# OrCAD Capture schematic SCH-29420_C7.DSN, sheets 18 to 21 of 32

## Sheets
18 P16_eMMC & SD_CARD: size A2
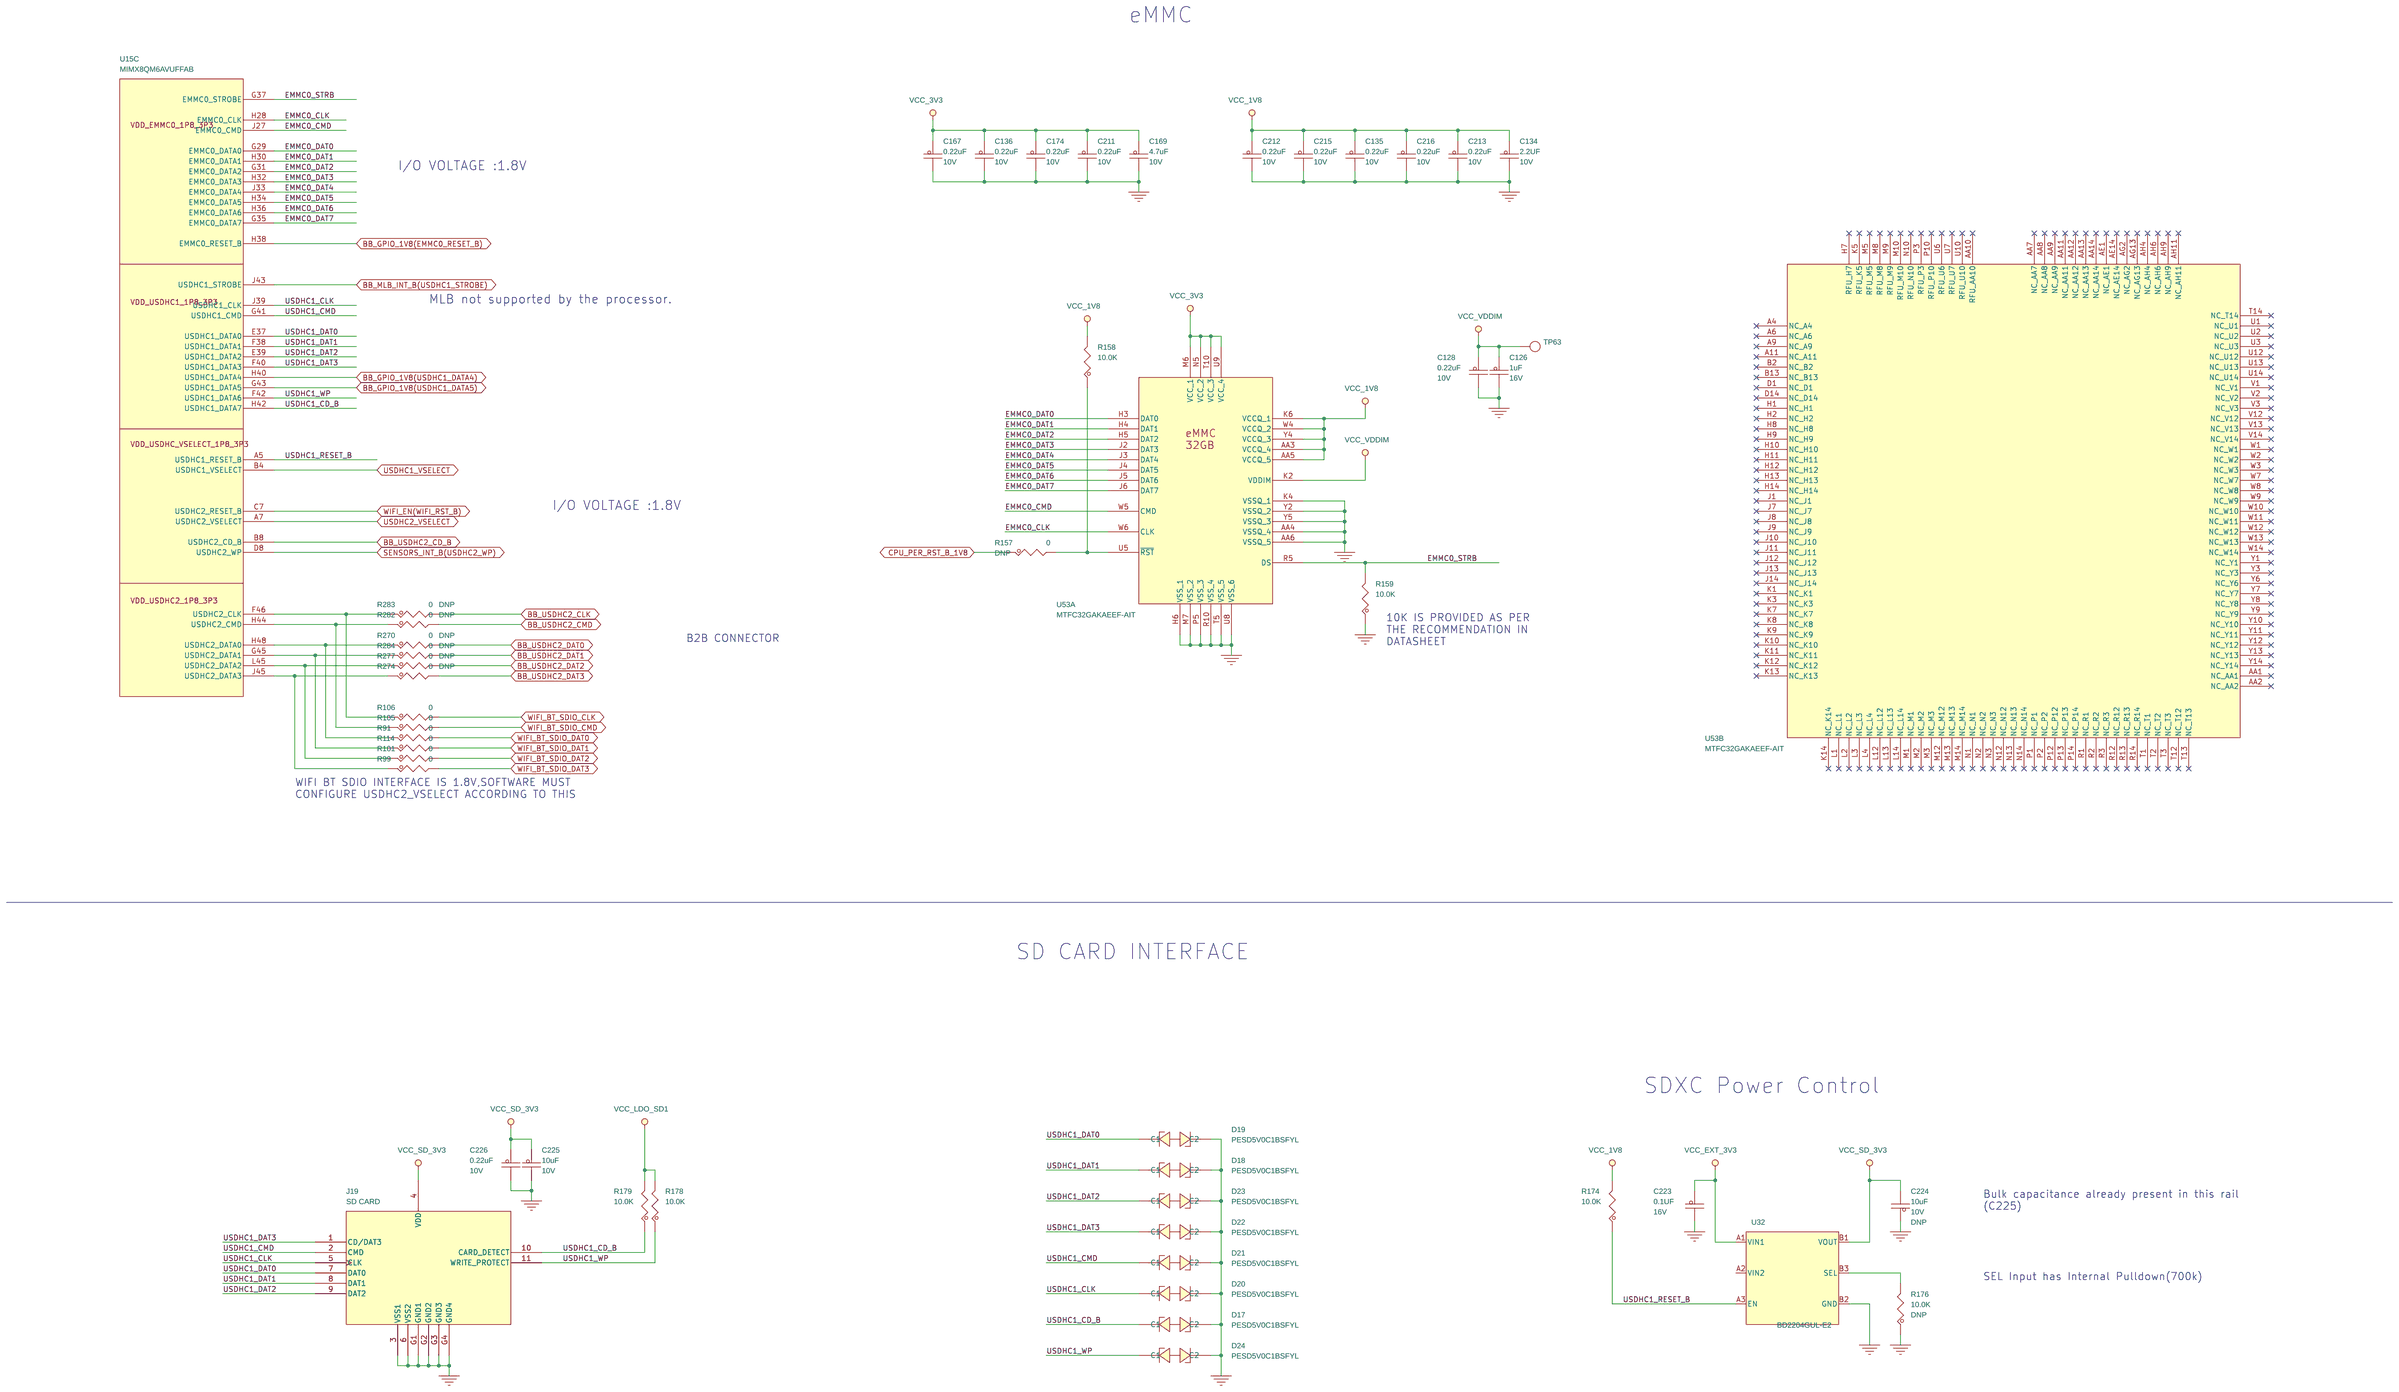
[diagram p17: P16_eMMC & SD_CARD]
19 P17_BOOT_CONFIG & SPI FLASH: size A2
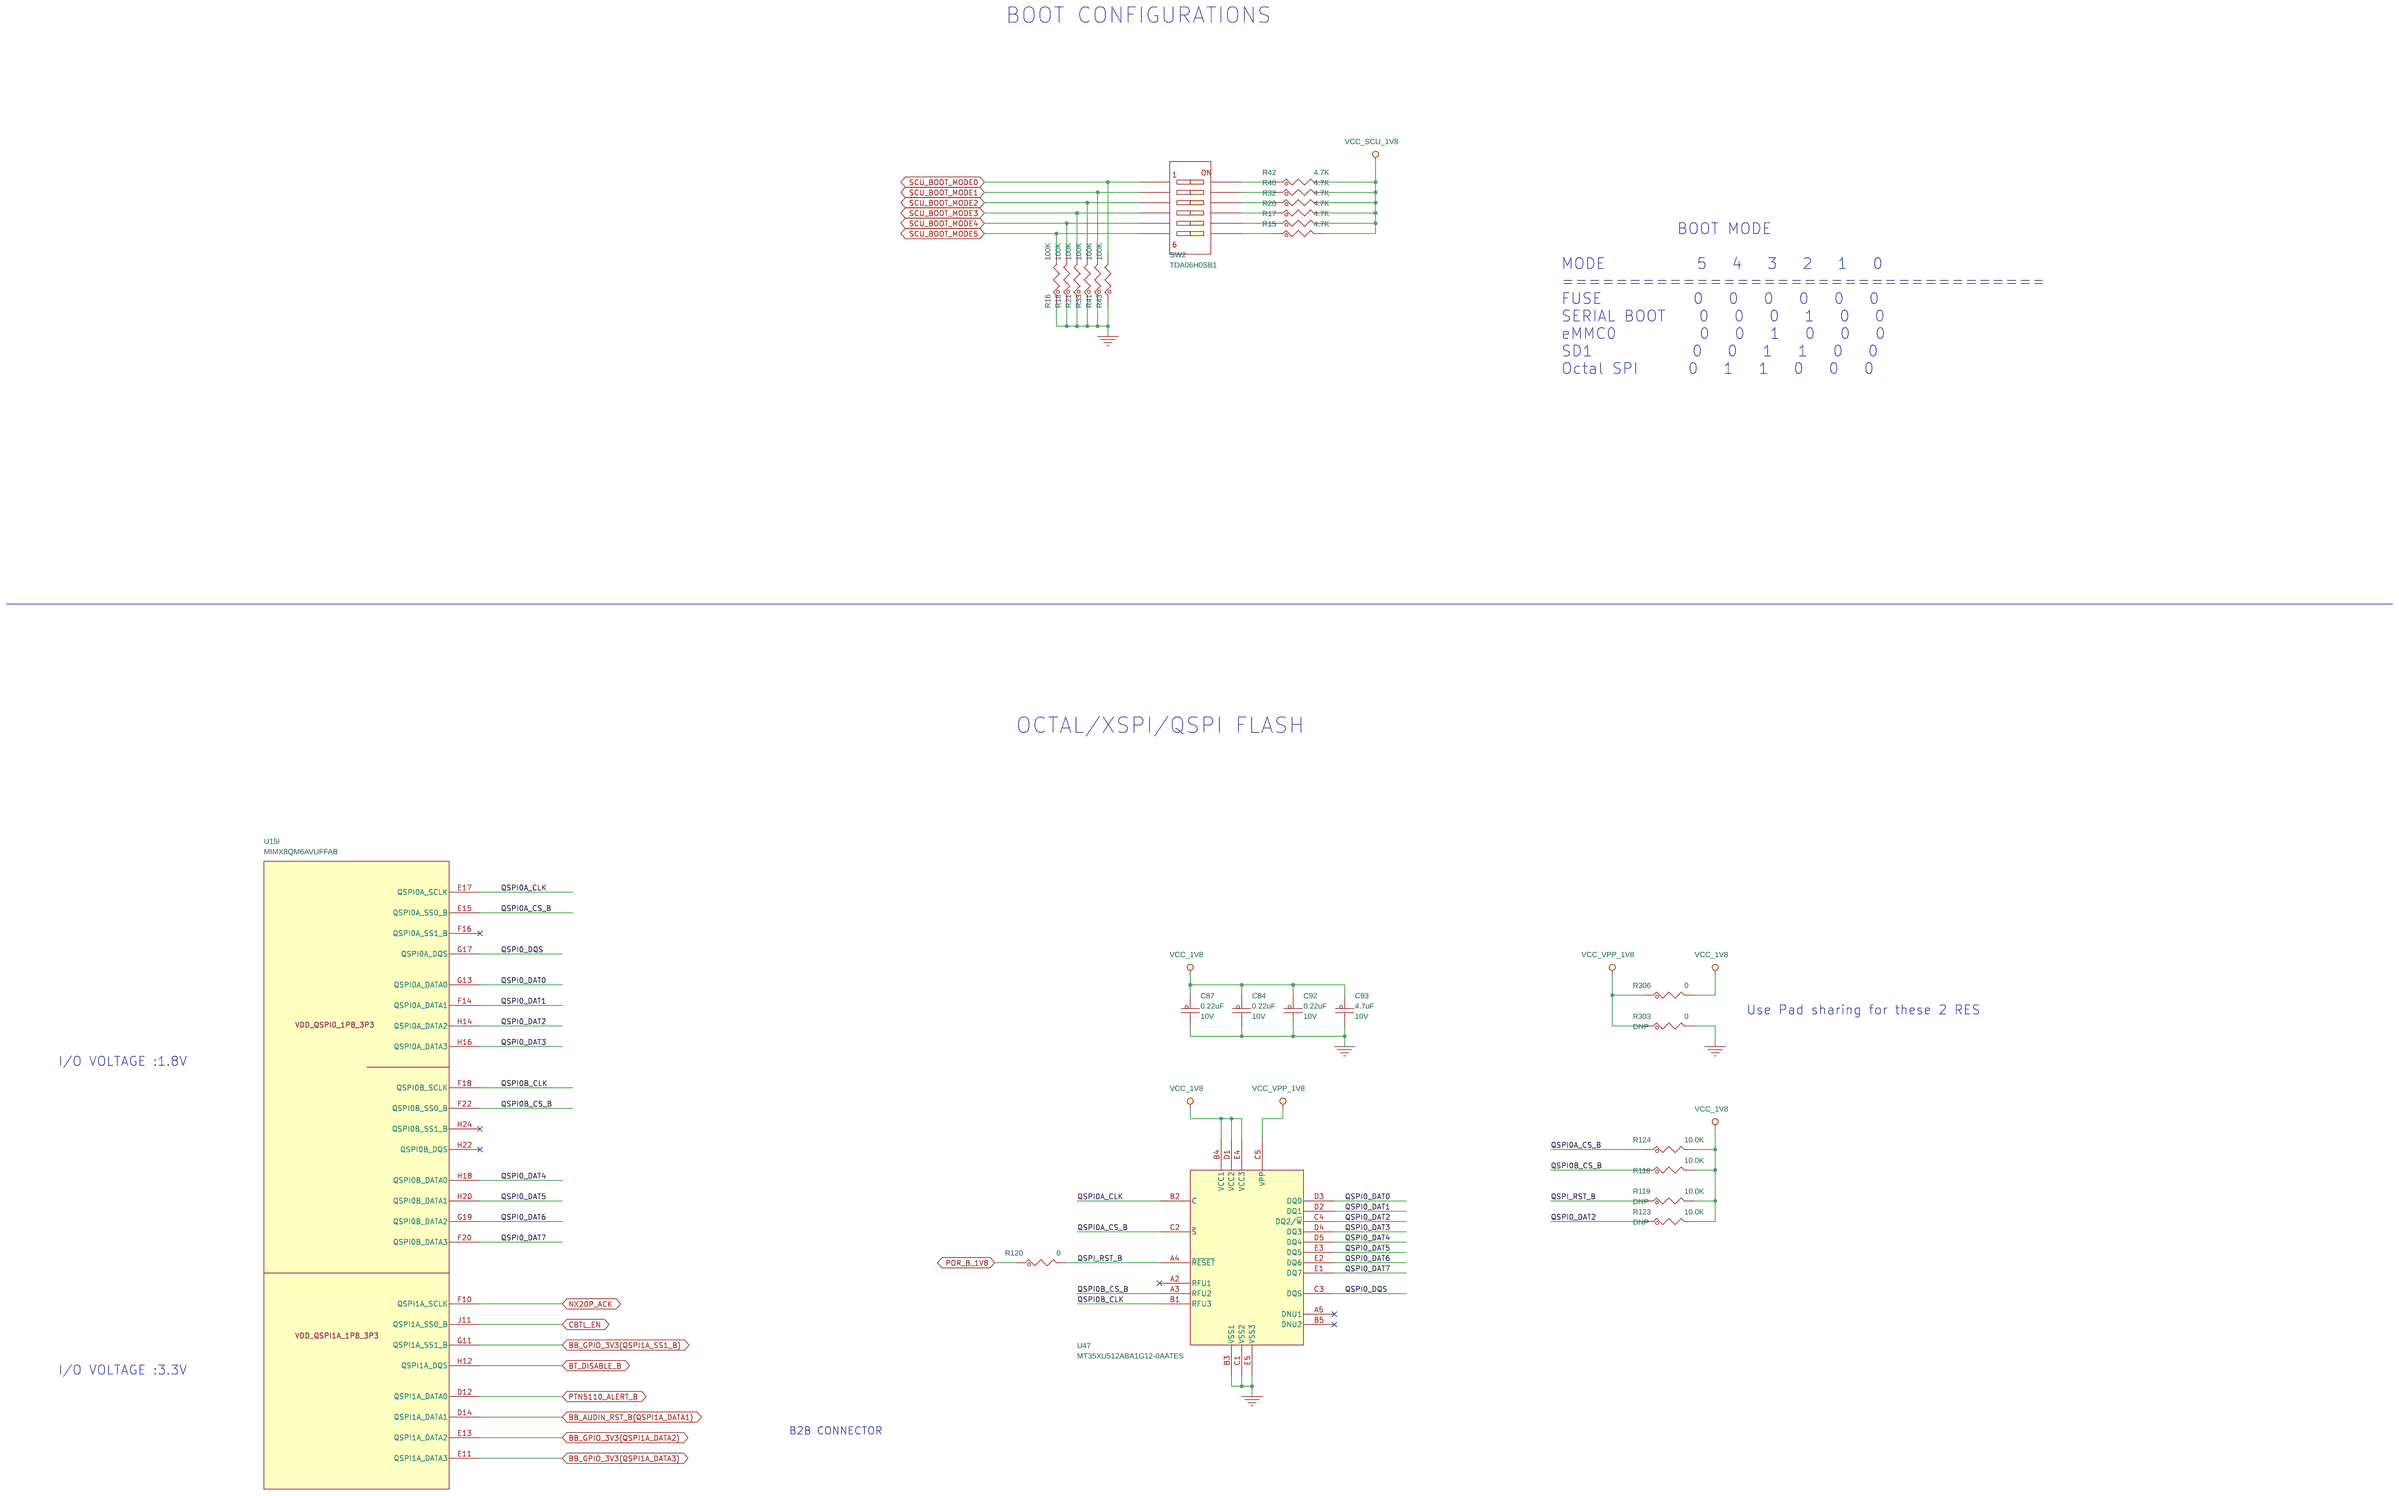
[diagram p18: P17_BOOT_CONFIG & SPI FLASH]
20 P18_RESET LOGIC_LEDS_JTAG: size A2
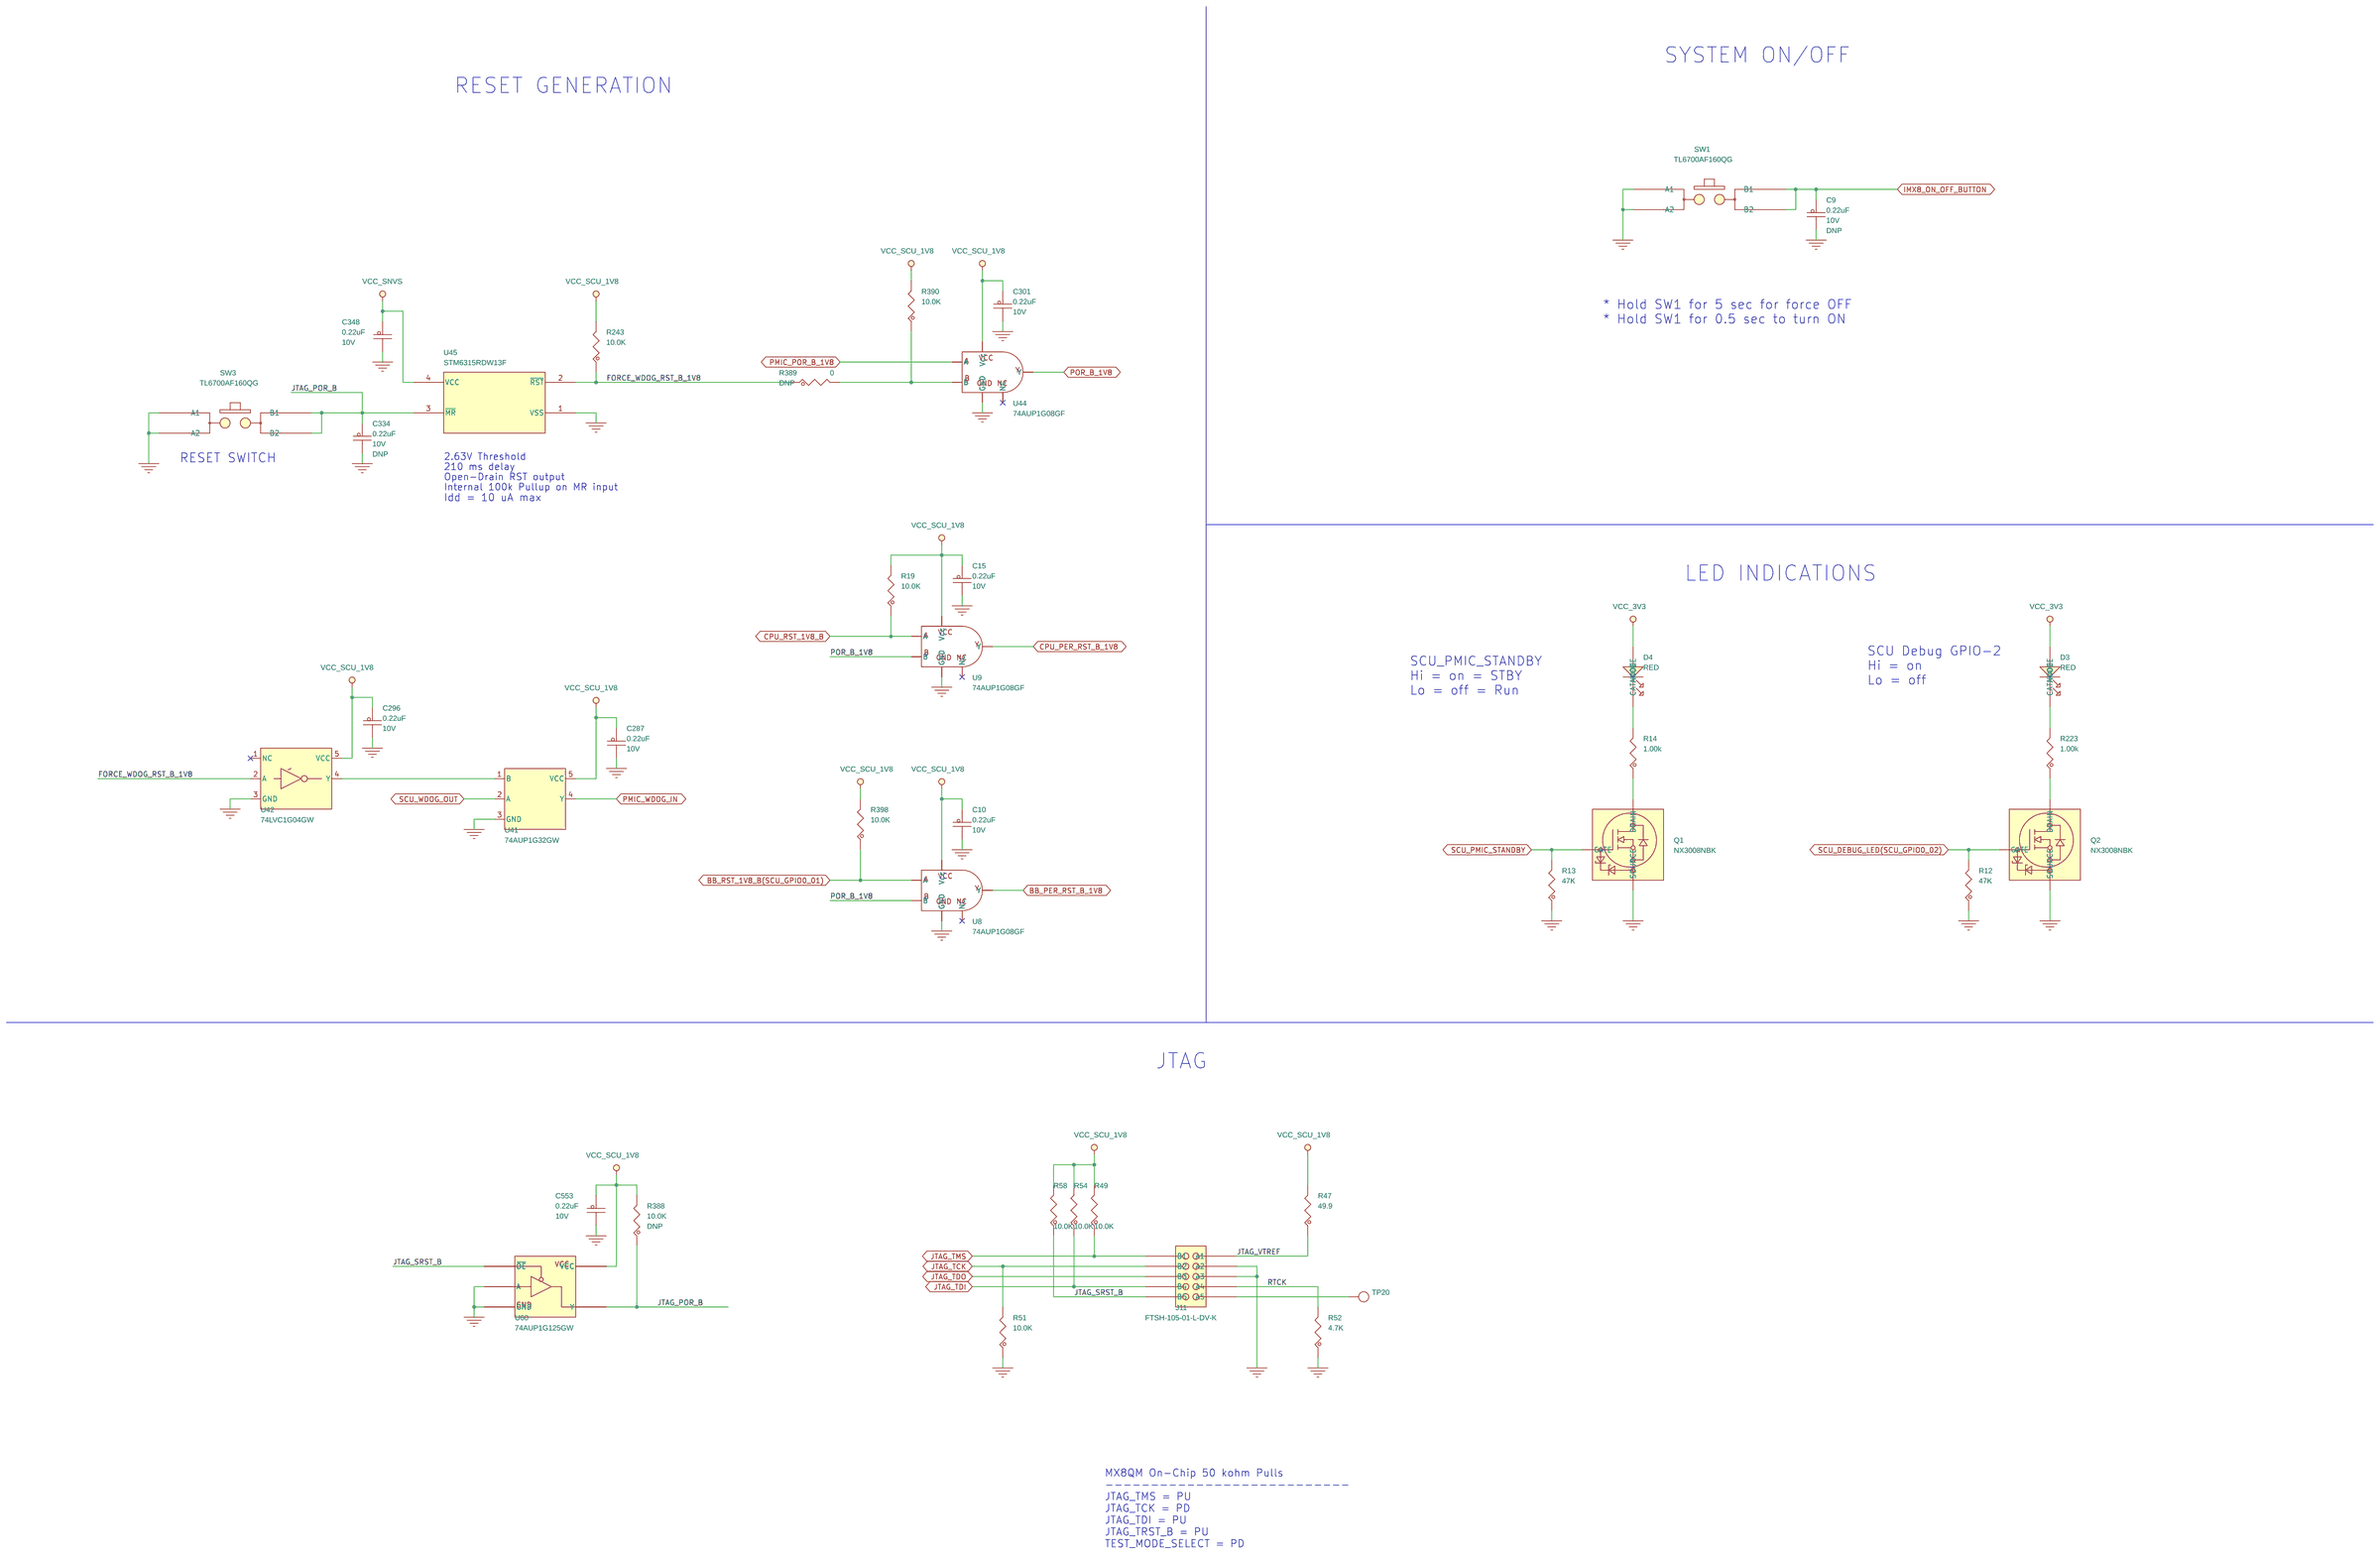
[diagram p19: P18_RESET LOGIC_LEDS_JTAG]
21 P19_DEBUG_UART_USB: size A2
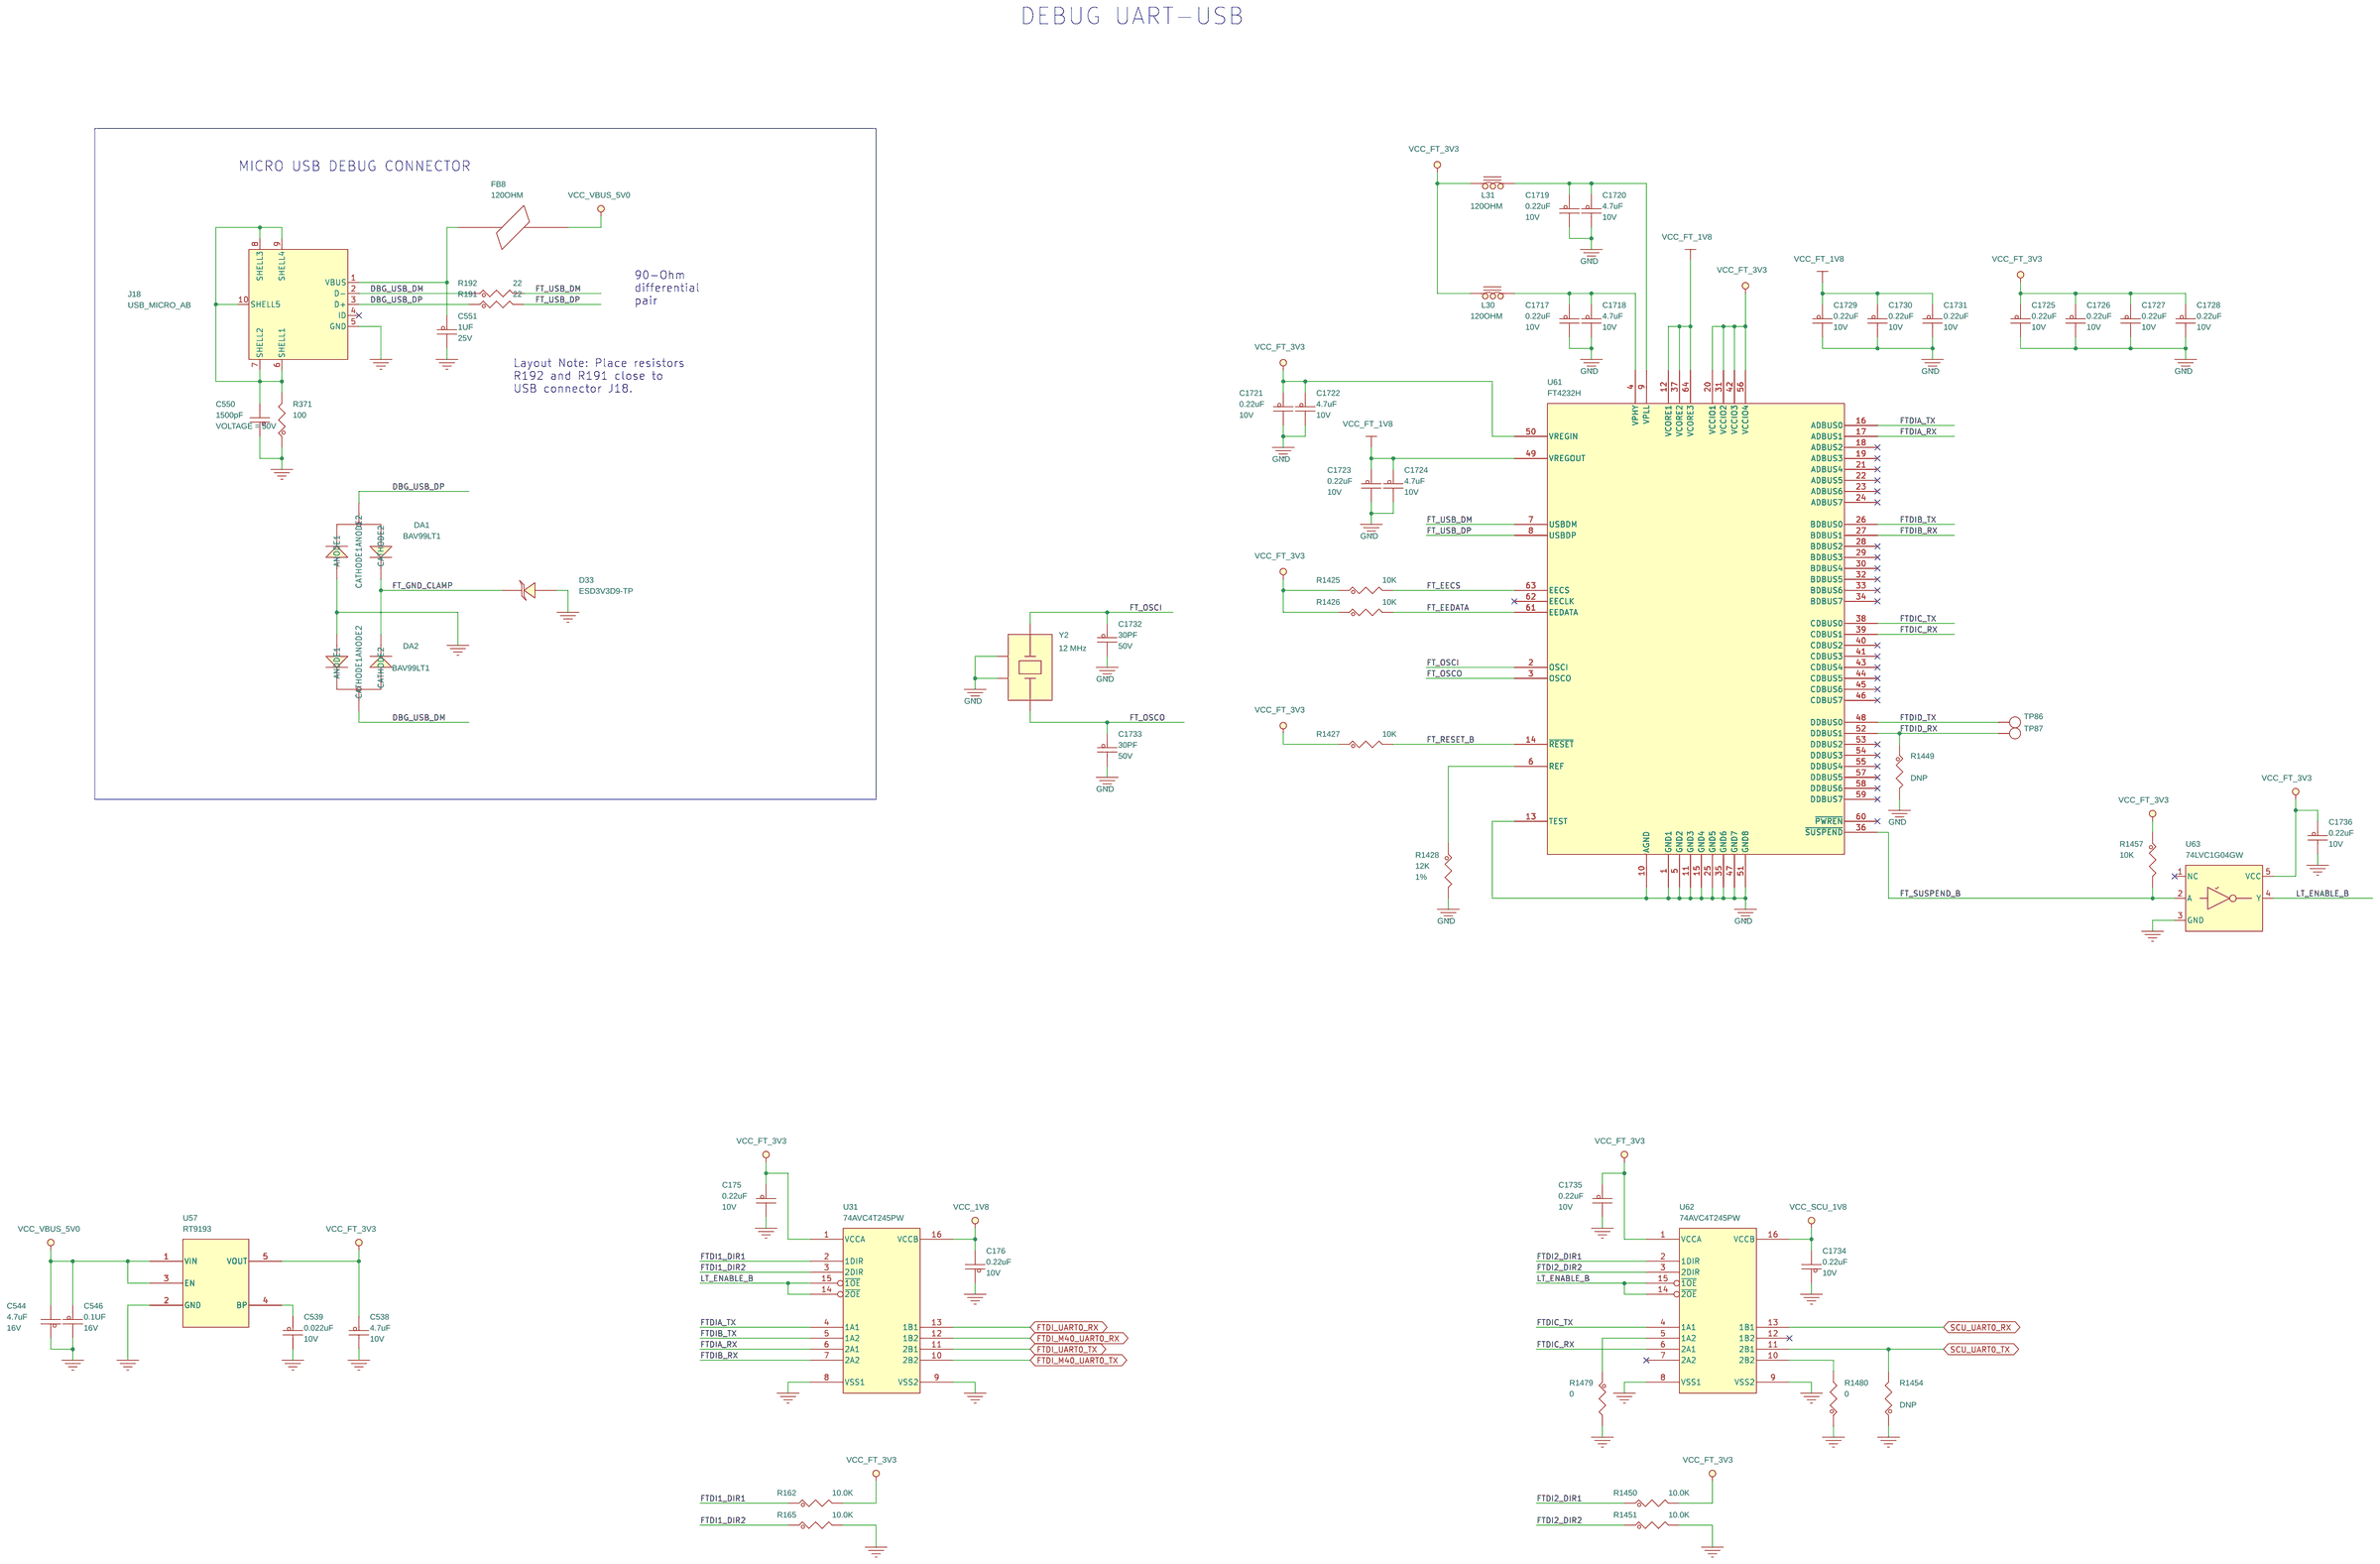
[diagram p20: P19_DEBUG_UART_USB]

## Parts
sheet P16_eMMC & SD_CARD
C126  1uF  [CC0402_25]
C128  0.22uF  [CC0402_25]
C134  2.2UF  [CC0402_25]
C135  0.22uF  [CC0402_25]
C136  0.22uF  [CC0402_25]
C167  0.22uF  [CC0402_25]
C169  4.7uF  [CC0402_25]
C174  0.22uF  [CC0402_25]
C211  0.22uF  [CC0402_25]
C212  0.22uF  [CC0402_25]
C213  0.22uF  [CC0402_25]
C215  0.22uF  [CC0402_25]
C216  0.22uF  [CC0402_25]
C223  0.1UF  [CC0402_25]
C224  10uF  [CC0603_OV]
C225  10uF  [CC0603_OV]
C226  0.22uF  [CC0402_25]
D17  PESD5V0C1BSFYL  [dsn0603-2]
D18  PESD5V0C1BSFYL  [dsn0603-2]
D19  PESD5V0C1BSFYL  [dsn0603-2]
D20  PESD5V0C1BSFYL  [dsn0603-2]
D21  PESD5V0C1BSFYL  [dsn0603-2]
D22  PESD5V0C1BSFYL  [dsn0603-2]
D23  PESD5V0C1BSFYL  [dsn0603-2]
D24  PESD5V0C1BSFYL  [dsn0603-2]
J19  SD CARD  [con_sdcard_26p7x16p7_sm_ra]
R91  0  [RC0402_25]
R99  0  [RC0402_25]
R101  0  [RC0402_25]
R105  0  [RC0402_25]
R106  0  [RC0402_25]
R114  0  [RC0402_25]
R157  0  [RC0402_25]
R158  10.0K  [RC0402_25]
R159  10.0K  [RC0402_25]
R174  10.0K  [RC0402_25]
R176  10.0K  [RC0402_25]
R178  10.0K  [RC0402_25]
R179  10.0K  [RC0402_25]
R270  0  [RC0402_25]
R274  0  [RC0402_25]
R277  0  [RC0402_25]
R282  0  [RC0402_25]
R283  0  [RC0402_25]
R284  0  [RC0402_25]
TP63  TPAD_050  [TPAD_050]
U32  BD2204GUL-E2  [csp6_0p5_1p55x1p05]
U53  MTFC32GAKAEEF-AIT  [fbga169_0p5_14x18]  (sections A,B)
sheet P17_BOOT_CONFIG & SPI FLASH
C84  0.22uF  [CC0402_25]
C87  0.22uF  [CC0402_25]
C92  0.22uF  [CC0402_25]
C93  4.7uF  [CC0402_25]
R15  4.7K  [RC0402_25]
R16  100K  [RC0402_25]
R17  4.7K  [RC0402_25]
R18  100K  [RC0402_25]
R20  4.7K  [RC0402_25]
R21  100K  [RC0402_25]
R32  4.7K  [RC0402_25]
R33  100K  [RC0402_25]
R40  4.7K  [RC0402_25]
R41  100K  [RC0402_25]
R42  4.7K  [RC0402_25]
R43  100K  [RC0402_25]
R118  10.0K  [RC0402_25]
R119  10.0K  [RC0402_25]
R120  0  [RC0402_25]
R123  10.0K  [RC0402_25]
R124  10.0K  [RC0402_25]
R303  0  [RC0402_25]
R306  0  [RC0402_25]
SW2  TDA06H0SB1  [sw_dip12_6pos_sm]
U47  MT35XU512ABA1G12-0AATES  [PBGA24_1_6X8MM]
sheet P18_RESET LOGIC_LEDS_JTAG
C9  0.22uF  [CC0402_25]
C10  0.22uF  [CC0402_25]
C15  0.22uF  [CC0402_25]
C287  0.22uF  [CC0402_25]
C296  0.22uF  [CC0402_25]
C301  0.22uF  [CC0402_25]
C334  0.22uF  [CC0402_25]
C348  0.22uF  [CC0402_25]
C553  0.22uF  [CC0402_25]
D3  RED  [LED_0603]
D4  RED  [LED_0603]
J11  FTSH-105-01-L-DV-K  [hdr205_10m_50_sm_k]
Q1  NX3008NBK  [SOT23_A]
Q2  NX3008NBK  [SOT23_A]
R12  47K  [RC0402_25]
R13  47K  [RC0402_25]
R14  1.00k  [RC0402_25]
R19  10.0K  [RC0402_25]
R47  49.9  [RC0402_25]
R49  10.0K  [RC0402_25]
R51  10.0K  [RC0402_25]
R52  4.7K  [RC0402_25]
R54  10.0K  [RC0402_25]
R58  10.0K  [RC0402_25]
R223  1.00k  [RC0402_25]
R243  10.0K  [RC0402_25]
R388  10.0K  [RC0402_25]
R389  0  [RC0402_25]
R390  10.0K  [RC0402_25]
R398  10.0K  [RC0402_25]
SW1  TL6700AF160QG  [sw4g_spst_6p9x6p2]
SW3  TL6700AF160QG  [sw4g_spst_6p9x6p2]
TP20  TPAD_050  [TPAD_050]
U8  74AUP1G08GF  [sot891_6p_0p35_1p05x1p05]
U9  74AUP1G08GF  [sot891_6p_0p35_1p05x1p05]
U41  74AUP1G32GW  [SC70-5]
U42  74LVC1G04GW  [sc70-5]
U44  74AUP1G08GF  [sot891_6p_0p35_1p05x1p05]
U45  STM6315RDW13F  [sot143-25x60]
U60  74AUP1G125GW  [SC70-5]
sheet P19_DEBUG_UART_USB
C175  0.22uF  [CC0402_25]
C176  0.22uF  [CC0402_25]
C538  4.7uF  [CC0402_25]
C539  0.022uF  [CC0402_25]
C544  4.7uF  [CC0603_OV]
C546  0.1UF  [CC0402_25]
C550  1500pF  [CC0402_25]
C551  1UF  [CC0603_OV]
C1717  0.22uF  [0402_CC]
C1718  4.7uF  [CC0402_25]
C1719  0.22uF  [0402_CC]
C1720  4.7uF  [CC0402_25]
C1721  0.22uF  [0402_CC]
C1722  4.7uF  [CC0402_25]
C1723  0.22uF  [0402_CC]
C1724  4.7uF  [CC0402_25]
C1725  0.22uF  [0402_CC]
C1726  0.22uF  [0402_CC]
C1727  0.22uF  [0402_CC]
C1728  0.22uF  [0402_CC]
C1729  0.22uF  [0402_CC]
C1730  0.22uF  [0402_CC]
C1731  0.22uF  [0402_CC]
C1732  30PF  [CC0402_25]
C1733  30PF  [CC0402_25]
C1734  0.22uF  [CC0402_25]
C1735  0.22uF  [CC0402_25]
C1736  0.22uF  [CC0402_25]
D33  ESD3V3D9-TP  [SOD-923]
DA1  BAV99LT1  [sot23_a]
DA2  BAV99LT1  [sot23_a]
FB8  120OHM  [IND_0603]
J18  USB_MICRO_AB  [con_microab_10f_25_sm_ra]
L30  120OHM  [0603_CC]
L31  120OHM  [0603_CC]
R162  10.0K  [RC0402_25]
R165  10.0K  [RC0402_25]
R191  22  [RC0402_25]
R192  22  [RC0402_25]
R371  100  [RC0402_25]
R1425  10K  [RC0402_25]
R1426  10K  [RC0402_25]
R1427  10K  [RC0402_25]
R1428  12K  [RC0402_25]
R1449  68K  [RC0402_25]
R1450  10.0K  [RC0402_25]
R1451  10.0K  [RC0402_25]
R1454  68K  [RC0402_25]
R1457  10K  [RC0402_25]
R1479  0  [RC0402_25]
R1480  0  [RC0402_25]
TP86  TPAD_050  [TPAD_050]
TP87  TPAD_050  [TPAD_050]
U31  74AVC4T245PW  [tssop16]
U57  RT9193  [sot23-5]
U61  FT4232H  [lqfp64_0p5_10x10]
U62  74AVC4T245PW  [tssop16]
U63  74LVC1G04GW  [sc70-5]
Y2  12 MHz  [xtal_4_3p3x2p6mm]
sheet P20_USB3.x_TYPE_C
U15  MIMX8QM6AVUFFAB  [imx8_bga_1313]  (sections A,B,C,D,E,F,G,H,I,J,K,L,M,N,O,P,Q,R,S,T,U)

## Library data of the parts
C126 = CAP_NP: CAP CER 1uF 16V 10% X5R 0402; AGILE_PN: 150-79794; CAD_APPROVED: Yes; EN: 102-1-01641; FPLIST: CC0402_25,CC0402_HD,0402_CC; HEIGHT: 0.55MM; MFG_NAME01: NIC COMPONENTS CORP; MFG_PN01: NMC0402X5R105K16TRPF; ROHS: Yes; TOL: +/-10%; Tolerance: +/-10%; VOLTAGE: 16V
C10 C15 C84 C87 C92 C128 C135 C136 C167 C174-C176 C211-C213 C215 C216 C226 C287 C296 C301 C348 C553 C1717 C1719 C1721 C1723 C1725-C1731 C1734-C1736 = CAP_NP: CAP CER 0.22uF 10V 10% X7R AEC-Q200 0402; AGILE_PN: 150-79031; CAD_APPROVED: Yes; EN: 102-1-01816; FPLIST: CC0402_25,CC0402_HD,0402_CC; HEIGHT: 0.55MM; MFG_NAME01: TDK; MFG_PN01: CGA2B1X7R1A224K050BC; ROHS: Yes; TOL: 10%; Tolerance: 10%; VOLTAGE: 10V
C134 = CAP_NP: CAP CER 2.2UF 10V 10% X5R 0402; AGILE_PN: 150-79475; CAD_APPROVED: Yes; EN: 102-1-00208; FPLIST: CC0402_25,CC0402_HD,0402_CC; HEIGHT: 0.56MM; MFG_NAME01: AVX; MFG_PN01: 0402ZD225KAT2A; ROHS: Yes; TOL: 10%; Tolerance: 10%; VOLTAGE: 10V
C93 C169 C538 C1718 C1720 C1722 C1724 = CAP_NP: CAP CER 4.7uF 10V 10% X5R 0402; AGILE_PN: 150-79778; CAD_APPROVED: Yes; EN: 102-1-02063; FPLIST: CC0402_25,CC0402_HD,0402_CC; HEIGHT: 0.65MM; MFG_NAME01: TDK; MFG_PN01: C1005X5R1A475K050BC; ROHS: Yes; TOL: 10%; Tolerance: 10%; VOLTAGE: 10V
C223 C546 = CAP_NP: CAP CER 0.1UF 16V 10% X7R 0402; AGILE_PN: 150-75182; CAD_APPROVED: Yes; EN: 102-1-01629; FPLIST: CC0402_25,CC0402_HD,0402_CC; HEIGHT: 0.635MM; MFG_NAME01: AVX; MFG_PN01: 0402YC104KAT2A; ROHS: Yes; TOL: 10%; Tolerance: 10%; VOLTAGE: 16V
C224 = CAP_NP: CAP CER 10UF 10V 20% X5R 0603; AGILE_PN: 150-78609; ASSY_OPT: DNP; CAD_APPROVED: Yes; EN: 102-1-01640; FPLIST: CC0603_OV,CC0603,0603_CC; HEIGHT: 1.016MM; MFG_NAME01: TAIYO YUDEN; MFG_PN01: LMK107BJ106MALTD; ROHS: Yes; VOLTAGE: 10V
C225 = CAP_NP: CAP CER 10UF 10V 20% X5R 0603; AGILE_PN: 150-78609; CAD_APPROVED: Yes; EN: 102-1-01640; FPLIST: CC0603_OV,CC0603,0603_CC; HEIGHT: 1.016MM; MFG_NAME01: TAIYO YUDEN; MFG_PN01: LMK107BJ106MALTD; ROHS: Yes; VOLTAGE: 10V
D17-D24 = DIODE_BIDIR: DIODE TVS 5VWM 6.5VC DSN0603-2; AGILE_PN: 480-79859; CAD_APPROVED: Yes; EN: 305-1-00288; HEIGHT: 0.32MM; MFG_NAME01: NEXPERIA; ROHS: Yes
J19 = CONN_SDCARD_PUSH_PULL_9P: CON 9 SD CARD PUSH-PULL SKT SMT RA 2.5MM SP 118H AU; AGILE_PN: 211-80157; CAD_APPROVED: Yes; EN: 201-2-00848; HEIGHT: 3MM; MFG_NAME01: WURTH ELEKTRONIK EISOS GMBH & CO. KG; MFG_PN01: 693063020911; ROHS: Yes; Temp_Range: -25C to +85C
R91 R99 R101 R105 R106 R114 R120 R306 R1479 R1480 = RES: RES MF ZERO OHM 1/16W -- AEC-Q200 0402; AGILE_PN: 470-80742; CAD_APPROVED: Yes; EN: 101-1-00001; FPLIST: RC0402_25,RC0402_HD,0402_CC; HEIGHT: 0.45 MM; MFG_NAME01: VISHAY INTERTECHNOLOGY; MFG_PN01: CRCW04020000Z0ED; ROHS: Yes
R157 R270 R274 R277 R282-R284 R303 R389 = RES: RES MF ZERO OHM 1/16W -- AEC-Q200 0402; AGILE_PN: 470-80742; ASSY_OPT: DNP; CAD_APPROVED: Yes; EN: 101-1-00001; FPLIST: RC0402_25,RC0402_HD,0402_CC; HEIGHT: 0.45 MM; MFG_NAME01: VISHAY INTERTECHNOLOGY; MFG_PN01: CRCW04020000Z0ED; ROHS: Yes
R19 R49 R51 R54 R58 R118 R124 R158 R159 R162 R165 R174 R178 R179 R243 R390 R398 R1450 R1451 = RES: RES MF 10.0K 1/16W 1% 0402; AGILE_PN: 470-80574; CAD_APPROVED: Yes; EN: 101-1-00389; FPLIST: RC0402_25,RC0402_HD,0402_CC; HEIGHT: 0.4MM; MFG_NAME01: WALSIN TECHNOLOGY CORP.; MFG_PN01: WR04X1002FTL; ROHS: Yes; TOL: 1%; Tolerance: 1%
R119 R123 R176 R388 = RES: RES MF 10.0K 1/16W 1% 0402; AGILE_PN: 470-80574; ASSY_OPT: DNP; CAD_APPROVED: Yes; EN: 101-1-00389; FPLIST: RC0402_25,RC0402_HD,0402_CC; HEIGHT: 0.4MM; MFG_NAME01: WALSIN TECHNOLOGY CORP.; MFG_PN01: WR04X1002FTL; ROHS: Yes; TOL: 1%; Tolerance: 1%
TP20 TP63 TP86 TP87 = TESTLOOP: TEST POINT PAD 50MIL DIA SMT, NO PART TO ORDER; AGILE_PN: 211-76644; CAD_APPROVED: Yes; HEIGHT: 0.1MM; MFG_NAME01: NOTACOMPONENT; MFG_PN01: NOTACOMPONENT; ROHS: Yes
U32 = BD2204GUL_6P: IC PWR DUAL SELECTOR SW LOGIC CONTROLED 1.2-4.5V VCSP50L1; AGILE_PN: 315-80675; CAD_APPROVED: Yes; EN: 301-4-00701; HEIGHT: 0.55MM; MFG_NAME01: ROHM; ROHS: Yes
U53 = MTFC32GAKAEEF_TFBGA_169P: IC MEM NAND FLASH 32GB EMMC 2.7-3.6V AUTO TFBGA169; AGILE_PN: 342-00634; CAD_APPROVED: Yes; EN: 301-2-00393; HEIGHT: 1.2MM; MFG_NAME01: Micron; ROHS: Yes
R15 R17 R20 R32 R40 R42 R52 = RES: RES MF 4.7K 1/16W 5% 0402; AGILE_PN: 470-75626; CAD_APPROVED: Yes; EN: 101-1-02785; FPLIST: RC0402_25,RC0402_HD,0402_CC,RC0402_X2; HEIGHT: 0.41mm; MFG_NAME01: NIC COMPONENTS CORP; MFG_PN01: NRCL04J472TRF; ROHS: Yes; TOL: 5%; Tolerance: 5%
R16 R18 R21 R33 R41 R43 = RES: RES MF 100K 1/16W 5% 0402; AGILE_PN: 470-75597; CAD_APPROVED: Yes; EN: 101-1-02817; FPLIST: RC0402_25,RC0402_HD,0402_CC; HEIGHT: 0.40 MM; MFG_NAME01: VENKEL COMPANY; MFG_PN01: CR0402-16W-104JT; ROHS: Yes; TOL: 5%; Tolerance: 5%
SW2 = SW_DIP-6_SMT: SW SPST DIP6 25MA 24V SMT; AGILE_PN: 510-77997; CAD_APPROVED: Yes; EN: 205-1-00024; HEIGHT: 2.3MM; MFG_NAME01: C&K Components; ROHS: Yes
U47 = MT35XU512ABA1G12: IC MEM FLASH SERIAL NOR 512MB 1.7-2.0V AUTO T-PBGA24; AGILE_PN: 342-00680; CAD_APPROVED: Yes; EN: 301-2-00388; HEIGHT: 1.2MM; MFG_NAME01: MICRON; ROHS: Yes
C9 C334 = CAP_NP: CAP CER 0.22uF 10V 10% X7R AEC-Q200 0402; AGILE_PN: 150-79031; ASSY_OPT: DNP; CAD_APPROVED: Yes; EN: 102-1-01816; FPLIST: CC0402_25,CC0402_HD,0402_CC; HEIGHT: 0.55MM; MFG_NAME01: TDK; MFG_PN01: CGA2B1X7R1A224K050BC; ROHS: Yes; TOL: 10%; Tolerance: 10%; VOLTAGE: 10V
D3 D4 = LED: LED RED SGL 20MA 0603; AGILE_PN: 370-76632; CAD_APPROVED: Yes; EN: 106-4-00247; HEIGHT: 0.45MM; MFG_NAME01: LITE ON; MFG_PN01: LTST-C193KRKT-5A; ROHS: Yes
J11 = CONN_HDR_5X2: HDR 2X5 SMT 50MIL CTR 246H AU; AGILE_PN: 211-79478; CAD_APPROVED: Yes; EN: 201-1-00325; HEIGHT: 6.25MM; MFG_NAME01: SAMTEC; ROHS: Yes
Q1 Q2 = NMOS_NX3008NBK: TRAN NMOS PWR 30V 400mA AEC-Q101 SOT23; AGILE_PN: 480-79305; CAD_APPROVED: Yes; EN: 107-2-00226; FPLIST: SOT23_A,TO-236; HEIGHT: 1.1MM; MFG_NAME01: NEXPERIA; MFG_PN01: NX3008NBK,215; ROHS: Yes
R12 R13 = RES: RES MF 47K 1/10W 1% AEC-Q200 0402; AGILE_PN: 470-81731; CAD_APPROVED: Yes; EN: 101-1-03402; FPLIST: RC0402_25,RC0402_HD,0402_CC; HEIGHT: 0.40 MM; MFG_NAME01: KOA SPEER; MFG_PN01: RK73H1ETTP4702F; ROHS: Yes; TOL: 1%; Temp_Range: -55C to +155C; Tolerance: 1%
R14 R223 = RES: RES MF 1.00k Ohm 1/16W 1% AEC-Q200 0402; AGILE_PN: 470-80511; CAD_APPROVED: Yes; EN: 101-1-00293; FPLIST: RC0402_25,RC0402_HD,0402_CC; HEIGHT: 0.4 MM; MFG_NAME01: KOA SPEER; MFG_PN01: RK73H1ETTP1001F; ROHS: Yes; TOL: 1%; Tolerance: 1%
R47 = RES: RES MF 49.9 OHM 1/16W 1% 0402; AGILE_PN: 470-75360; CAD_APPROVED: Yes; EN: 101-1-00168; FPLIST: RC0402_25,RC0402_HD,0402_CC; HEIGHT: 0.4MM; MFG_NAME01: BOURNS; MFG_PN01: CR0402-FX-49R9GLF; ROHS: Yes; TOL: 1%; Tolerance: 1%
SW1 SW3 = SW_PB_ESW: SW SPST PB 50mA 12V SMT; AGILE_PN: 510-77753; CAD_APPROVED: Yes; EN: 205-1-00113; HEIGHT: 3.75MM; MFG_NAME01: E SWITCH; ROHS: Yes
U8 U9 U44 = GATE_AND_2IN_6P: IC GATE AND 2 INPUT 0.8-3.6V XSON6; AGILE_PN: 312-81802; CAD_APPROVED: Yes; EN: 301-0-00495; HEIGHT: 0.5MM; MFG_NAME01: NEXPERIA; MFG_PN01: 74AUP1G08GF,132; ROHS: Yes; Temp_Range: -40C to 125C
U41 = 74AUP1G32_5P: IC GATE OR 2 INPUT 0.8-3.6V TSSOP5; AGILE_PN: 312-81147; CAD_APPROVED: Yes; EN: 301-0-01516; HEIGHT: 1.1 MM; MFG_NAME01: NEXPERIA; MFG_PN01: 74AUP1G32GW,125; ROHS: Yes
U42 U63 = NC7SZ14: IC INV SGL 1.65-5.5V TSSOP5; AGILE_PN: 315-81077; CAD_APPROVED: Yes; EN: 301-0-01255; HEIGHT: 1.1MM; MFG_NAME01: NEXPERIA; MFG_PN01: 74LVC1G04GW,125; ROHS: Yes
U45 = STM6315RDW13F: IC MPU RESET CIRC 2.63V 1.0-5.5V SOT143-4; AGILE_PN: 312-79199; CAD_APPROVED: Yes; EN: 301-0-00338; HEIGHT: 1.12MM; MFG_NAME01: ST MICROELECTRONICS; ROHS: Yes
U60 = 1G125: IC BUFFER/LINE DRIVER 3STATE 0.8-3.6V SC70-5; AGILE_PN: 315-80956; CAD_APPROVED: Yes; EN: 301-0-01520; HEIGHT: 1.1MM; MFG_NAME01: NEXPERIA; MFG_PN01: 74AUP1G125GW,125; ROHS: Yes
C539 = CAP_NP: CAP CER 0.022uF 10V 10% X7R 0402; AGILE_PN: 150-80102; CAD_APPROVED: Yes; EN: 102-1-00005; FPLIST: CC0402_25,CC0402_HD,0402_CC; HEIGHT: 0.56MM; MFG_NAME01: AVX; MFG_PN01: 0402ZC223KAT2A; ROHS: Yes; TOL: 10%; Temp_Range: -55°C ~ 125°C; Tolerance: 10%; VOLTAGE: 10V
C544 = CAP_NP: CAP CER 4.7uF 16V 10% X5R 0603; AGILE_PN: 150-78976; CAD_APPROVED: Yes; EN: 102-1-00091; FPLIST: CC0603_OV,CC0603,0603_CC; HEIGHT: 0.9 MM; MFG_NAME01: TDK; MFG_PN01: C1608X5R1C475K080AC; ROHS: Yes; TOL: 10%; Tolerance: 10%; VOLTAGE: 16V
C550 = CAP_NP: CAP CER 1500PF 50V 10% X7R 0402; AGILE_PN: 150-76273; CAD_APPROVED: Yes; EN: 102-1-00058; FPLIST: CC0402_25,CC0402_HD,0402_CC; HEIGHT: 0.55MM; MFG_NAME01: AVX; MFG_PN01: 04025C152KAT2A; ROHS: Yes; TOL: 10%; Tolerance: 10%; VOLTAGE: 50V
C551 = CAP_NP: CAP CER 1.0UF 25V 10% X5R 0603; AGILE_PN: 150-78563; CAD_APPROVED: Yes; EN: 102-1-01668; FPLIST: CC0603_OV,CC0603,0603_CC; HEIGHT: 0.95MM; MFG_NAME01: AVX; MFG_PN01: 06033D105KAT2A; ROHS: Yes; VOLTAGE: 25V
C1732 C1733 = CAP_NP: CAP CER 30PF 50V 5% C0G 0402; AGILE_PN: 150-77682; CAD_APPROVED: Yes; EN: 102-1-01740; FPLIST: CC0402_25,CC0402_HD,0402_CC; HEIGHT: 0.55MM; MFG_NAME01: MURATA; MFG_PN01: GRM1555C1H300JA01D; ROHS: Yes; TOL: 5%; VOLTAGE: 50V
D33 = DIODE_TVS: DIODE UNIDIR ESD PROT 100W@20uS 3.3V SOD-923; AGILE_PN: 480-78485; CAD_APPROVED: Yes; EN: 305-1-00239; HEIGHT: 0.43MM; MFG_NAME01: MICRO COMMERCIAL COMPONENTS CORP; ROHS: Yes
DA1 DA2 = DUALDIODE_SERIES_SOT23: DIODE DUAL SW 215MA 70V SOT23; AGILE_PN: 480-76339; CAD_APPROVED: Yes; EN No.: 106-0-00007; HEIGHT: 1.11MM; MFG_NAME01: ON SEMICONDUCTOR; MFG_PN01: BAV99LT1G; VOLTAGE: 70V
FB8 = BEAD_FERRITE: IND FER BEAD 120OHM@100MHZ 2A 25% 0603; AGILE_PN: 180-30008; CAD_APPROVED: Yes; EN: 104-1-00022; FPLIST: IND_0603,0603_CC; HEIGHT: 0.95MM; MFG_NAME01: MURATA; MFG_PN01: BLM18PG121SH1; PART_TYPE: FERRITE; ROHS: Yes; TOL: 25%; Tolerance: 25%
J18 = MICRO_USB_CONN_10PIN: CON 5 USB_MICRO_AB_RECEPTACLE RA SKT SMT 0.65MM SP 122H AU; AGILE_PN: 211-78945; CAD_APPROVED: Yes; EN: 201-2-00930; HEIGHT: 3.1MM; MFG_NAME01: molex; MFG_PN01: 0475900001; ROHS: Yes
L30 L31 = BEAD_0: IND FER BEAD 120OHM@100MHZ 2A 25% 0603; AGILE_PN: 180-30008; CAD_APPROVED: Yes; EN: 104-1-00022; FPLIST: IND_0603,0603_CC; HEIGHT: 0.95MM; MFG_NAME01: MURATA; MFG_PN01: BLM18PG121SH1; PART_TYPE: FERRITE; PRIORITY_PN: 024-00067; ROHS: Yes; ROOM: RGMII_PHY; TOL: 25%; Tolerance: 25%
R191 R192 = RES: RES MF 22 OHM 1/16W 5% 0402; AGILE_PN: 470-75605; CAD_APPROVED: Yes; EN: 101-1-03406; FPLIST: RC0402_25,RC0402_HD,0402_CC; HEIGHT: 0.4MM; MFG_NAME01: BOURNS; MFG_PN01: CR0402-JW-220GLF; ROHS: Yes; TOL: 5%; Tolerance: 5%
R371 = RES: RES MF 100 OHM 1/16W 5% AEC-Q200 0402; AGILE_PN: 470-80555; CAD_APPROVED: Yes; EN: 101-1-02745; FPLIST: RC0402_25,RC0402_HD,RC0402_X2,0402_CC; HEIGHT: 0.45mm; MFG_NAME01: VISHAY INTERTECHNOLOGY; MFG_PN01: CRCW0402100RJNED; ROHS: Yes
R1425-R1427 R1457 = RES: RES MF 10K 1/16W 5% 0402; AGILE_PN: 470-75557; CAD_APPROVED: Yes; EN: 101-1-02793; FPLIST: RC0402_25,RC0402_HD,0402_CC; HEIGHT: 0.4 MM; MFG_NAME01: VISHAY INTERTECHNOLOGY; MFG_PN01: CRCW040210K0JNED; ROHS: Yes; TOL: 5%; Tolerance: 5%
R1428 = RES: RES MF 12K 1/10W 1% AEC-Q200 0402; AGILE_PN: 470-30955; CAD_APPROVED: Yes; EN: 101-1-03373; FPLIST: RC0402_25,RC0402_HD,0402_CC; HEIGHT: 0.40 MM; MFG_NAME01: KOA SPEER; MFG_PN01: RK73H1ETTP1202F; ROHS: Yes; TOL: 1%
R1449 R1454 = RES: RES MF 68K  1/16W 1% AEC-Q200 0402; AGILE_PN: 470-31042; ASSY_OPT: DNP; CAD_APPROVED: Yes; EN: 101-1-03542; FPLIST: RC0402_25,RC0402_HD,0402_CC; HEIGHT: 0.40 MM; MFG_NAME01: VISHAY INTERTECHNOLOGY; MFG_PN01: CRCW040268K0FKED; PRIORITY_PN: 006-00730; ROHS: Yes; ROOM: JTAG; SIGNAL_MODEL: DEFAULT_RESISTOR_68000OHM_2_1; TOL: 1%; Tolerance: 1%
U31 U62 = SN74AVCH4T245: IC XCVR VXLTR 4BIT 0.8-3.6V TSSOP16; AGILE_PN: 312-80575; CAD_APPROVED: Yes; EN: 301-0-01648; HEIGHT: 1.1MM; MFG_NAME01: NEXPERIA; MFG_PN01: 74AVC4T245PW,118; ROHS: Yes
U57 = RT9193-33PB: IC VREG LDO 3.3V 300MA SOT-23-5; AGILE_PN: 315-76265; CAD_APPROVED: Yes; EN: 301-4-00617; HEIGHT: 1.295MM; MFG_NAME01: RICHTEK; ROHS: Yes
U61 = FT4232HL_LQFP64: IC QUAD USB UART/FIFO 3.3V LQFP64; AGILE_PN: 312-81268; CAD_APPROVED: Yes; EN: 301-0-02252; HEIGHT: 1.6MM; MFG_NAME01: FUTURE TECHNOLOGY DEVICES INTERNATIONAL LTD.; MFG_PN01: FT4232HL-REEL; ROHS: Yes
Y2 = XTAL_13: XTAL 12Mhz 18pF -- SMD; AGILE_PN: 230-77934; CAD_APPROVED: Yes; EN: 108-1-00213; HEIGHT: 0.8 MM; MFG_NAME01: TXC CORP; MFG_PN01: 7M-12.000MAAJ-T; ROHS: Yes
U15 = PIMX8QM6AVUFFAB_BGA1313: IC CPU QUADMAX 2xA72 1.6GHz 4xA53 1.2GHZ M4 264MHZ FCPBGA1313; AGILE_PN: 330-77094; CAD_APPROVED: Yes; HEIGHT: 2.52MM; MFG_NAME01: NXP SEMICONDUCTORS; ROHS: Yes; Temp Range: -40°C to 125°C

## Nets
GND: C9.2 C10.2 C15.2 C84.2 C87.2 C92.2 C93.2 C126.2 C128.2 C134.2 C135.2 C136.2 C167.2 C169.2 C174.2 C175.2 C176.1 C211.2 C212.2 C213.2 C215.2 C216.2 C223.2 C224.1 C225.2 C226.2 C287.2 C296.2 C301.2 C334.2 C348.2 C538.2 C539.2 C544.1 C546.2 C550.1 C551.2 C553.2 C1717.2 C1718.2 C1719.2 C1720.2 C1721.2 C1722.2 C1723.2 C1724.2 C1725.2 C1726.2 C1727.2 C1728.2 C1729.2 C1730.2 C1731.2 C1732.2 C1733.2 C1734.1 C1735.2 C1736.2 D17.2(C2) D18.2(C2) D19.2(C2) D20.2(C2) D21.2(C2) D22.2(C2) D23.2(C2) D24.2(C2) D33.A DA1.1(ANODE1) DA2.1(ANODE1) J11.3(A2) J11.5(A3) J18.5(GND) J19.3(VSS1) J19.6(VSS2) J19.G1(GND1) J19.G2(GND2) J19.G3(GND3) J19.G4(GND4) Q1.2(SOURCE) Q2.2(SOURCE) R12.1 R13.1 R16.1 R18.1 R21.1 R33.1 R41.1 R43.1 R51.1 R52.1 R159.1 R165.2 R176.1 R303.2 R371.1 R1428.2 R1449.2 R1451.2 R1454.1 R1479.2 R1480.1 SW1.1(A1) SW1.2(A2) SW3.1(A1) SW3.2(A2) U8.3(GND) U9.3(GND) U31.8(VSS1) U31.9(VSS2) U32.B2(GND) U41.3(GND) U42.3(GND) U44.3(GND) U45.1(VSS) U47.B3(VSS1) U47.C1(VSS2) U47.E5(VSS3) U53.AA4(VSSQ_4) U53.AA6(VSSQ_5) U53.H6(VSS_1) U53.K4(VSSQ_1) U53.M7(VSS_2) U53.P5(VSS_3) U53.R10(VSS_4) U53.T5(VSS_5) U53.U8(VSS_6) U53.Y2(VSSQ_2) U53.Y5(VSSQ_3) U57.2(GND) U60.2(A) U60.3(GND) U61.1(GND1) U61.5(GND2) U61.10(AGND) U61.11(GND3) U61.13(TEST) U61.15(GND4) U61.25(GND5) U61.35(GND6) U61.47(GND7) U61.51(GND8) U62.8(VSS1) U62.9(VSS2) U63.3(GND) Y2.2 Y2.4 ; also on sheet 2 5 6 10 11 12 13 14 16 17 22 23 24 25 26 27 28 29 30 31 32
VCC_1V8: C84.1 C87.1 C92.1 C93.1 C134.1 C135.1 C176.2 C212.1 C213.1 C215.1 C216.1 R118.2 R119.2 R123.2 R124.2 R158.2 R174.2 R306.2 U31.16(VCCB) U47.B4(VCC1) U47.D1(VCC2) U47.E4(VCC3) U53.AA3(VCCQ_4) U53.AA5(VCCQ_5) U53.K6(VCCQ_1) U53.W4(VCCQ_2) U53.Y4(VCCQ_3) ; also on sheet 2 6 10 11 12 15 16 17 24 27 28 31
VCC_3V3: C136.1 C167.1 C169.1 C174.1 C211.1 D3.A(ANODE) D4.A(ANODE) U53.M6(VCC_1) U53.N5(VCC_2) U53.T10(VCC_3) U53.U9(VCC_4) ; also on sheet 6 10 12 22 23 24 25 27 28 31
VCC_EXT_3V3: C223.1 U32.A1(VIN1) ; also on sheet 6 10 11
VCC_FT_1V8: C1723.1 C1724.1 C1729.1 C1730.1 C1731.1 U61.12(VCORE1) U61.37(VCORE2) U61.49(VREGOUT) U61.64(VCORE3)
VCC_FT_3V3: C175.1 C538.1 C1721.1 C1722.1 C1725.1 C1726.1 C1727.1 C1728.1 C1735.1 C1736.1 L30.1 L31.1 R162.2 R1425.1 R1426.1 R1427.1 R1450.2 R1457.1 U31.1(VCCA) U57.5(VOUT) U61.20(VCCIO1) U61.31(VCCIO2) U61.42(VCCIO3) U61.50(VREGIN) U61.56(VCCIO4) U62.1(VCCA) U63.5(VCC)
VCC_LDO_SD1: R178.2 R179.2 ; also on sheet 11 12
VCC_SCU_1V8: C10.1 C15.1 C287.1 C296.1 C301.1 C553.1 C1734.2 R15.2 R17.2 R19.2 R20.2 R32.2 R40.2 R42.2 R47.2 R49.2 R54.2 R58.2 R243.2 R388.2 R390.2 R398.2 U8.6(Vcc) U9.6(Vcc) U41.5(VCC) U42.5(VCC) U44.6(Vcc) U60.5(VCC) U62.16(VCCB) ; also on sheet 6 11 12 14
VCC_SD_3V3: C224.2 C225.1 C226.1 J19.4(VDD) U32.B1(VOUT)
VCC_SNVS: C348.1 U45.4(VCC) ; also on sheet 11 12
VCC_VBUS_5V0: C544.2 C546.1 FB8.2 U57.1(VIN) U57.3(EN)
VCC_VDDIM: C126.1 C128.1 TP63.1(Pin1) U53.K2(VDDIM)
VCC_VPP_1V8: R303.1 R306.1 U47.C5(VPP)
VIN2: U32.A2(VIN2)
BB_AUDIN_RST_B(QSPI1A_DATA1): U15.D14(QSPI1A_DATA1) ; also on sheet 2
BB_GPIO_1V8(EMMC0_RESET_B): U15.H38(EMMC0_RESET_B) ; also on sheet 2
BB_GPIO_1V8(USDHC1_DATA4): U15.H40(USDHC1_DATA4) ; also on sheet 2
BB_GPIO_1V8(USDHC1_DATA5): U15.G43(USDHC1_DATA5) ; also on sheet 2
BB_GPIO_3V3(QSPI1A_DATA2): U15.E13(QSPI1A_DATA2) ; also on sheet 2
BB_GPIO_3V3(QSPI1A_DATA3): U15.E11(QSPI1A_DATA3) ; also on sheet 2
BB_GPIO_3V3(QSPI1A_SS1_B): U15.G11(QSPI1A_SS1_B) ; also on sheet 2
BB_MLB_INT_B(USDHC1_STROBE): U15.J43(USDHC1_STROBE) ; also on sheet 2
BB_PER_RST_B_1V8: U8.4(Y) ; also on sheet 31
BB_RST_1V8_B(SCU_GPIO0_01): R398.1 U8.2(A) ; also on sheet 14
BB_USDHC2_CD_B: U15.B8(USDHC2_CD_B) ; also on sheet 2
BB_USDHC2_CLK: R283.2 ; also on sheet 2
BB_USDHC2_CMD: R282.2 ; also on sheet 2
BB_USDHC2_DAT0: R270.2 ; also on sheet 2
BB_USDHC2_DAT1: R284.2 ; also on sheet 2
BB_USDHC2_DAT2: R277.2 ; also on sheet 2
BB_USDHC2_DAT3: R274.2 ; also on sheet 2
BT_DISABLE_B: U15.H12(QSPI1A_DQS) ; also on sheet 26
CBTL_EN: U15.J11(QSPI1A_SS0_B) ; also on sheet 22
CPU_PER_RST_B_1V8: R157.1 U9.4(Y) ; also on sheet 31
CPU_RST_1V8_B: R19.1 U9.2(A) ; also on sheet 14
DBG_USB_DM: DA2.3(CATHODE1ANODE2) J18.2(D-) R192.1
DBG_USB_DP: DA1.3(CATHODE1ANODE2) J18.3(D+) R191.1
EMMC0_CLK: U15.H28(EMMC0_CLK) U53.W6(CLK)
EMMC0_CMD: U15.J27(EMMC0_CMD) U53.W5(CMD)
EMMC0_DAT0: U15.G29(EMMC0_DATA0) U53.H3(DAT0)
EMMC0_DAT1: U15.H30(EMMC0_DATA1) U53.H4(DAT1)
EMMC0_DAT2: U15.G31(EMMC0_DATA2) U53.H5(DAT2)
EMMC0_DAT3: U15.H32(EMMC0_DATA3) U53.J2(DAT3)
EMMC0_DAT4: U15.J33(EMMC0_DATA4) U53.J3(DAT4)
EMMC0_DAT5: U15.H34(EMMC0_DATA5) U53.J4(DAT5)
EMMC0_DAT6: U15.H36(EMMC0_DATA6) U53.J5(DAT6)
EMMC0_DAT7: U15.G35(EMMC0_DATA7) U53.J6(DAT7)
EMMC0_STRB: R159.2 U15.G37(EMMC0_STROBE) U53.R5(DS)
FORCE_WDOG_RST_B_1V8: R243.1 R389.1 U42.2(A) U45.2(~{RST})
FT_EECS: R1425.2 U61.63(EECS)
FT_EEDATA: R1426.2 U61.61(EEDATA)
FT_GND_CLAMP: D33.C DA1.2(CATHODE2) DA2.2(CATHODE2)
FT_OSCI: C1732.1 U61.2(OSCI) Y2.1
FT_OSCO: C1733.1 U61.3(OSCO) Y2.3
FT_RESET_B: R1427.2 U61.14(~{RESET})
FT_SUSPEND_B: R1457.2 U61.36(~{SUSPEND}) U63.2(A)
FT_USB_DM: R192.2 U61.7(USBDM)
FT_USB_DP: R191.2 U61.8(USBDP)
FTDI1_DIR1: R162.1 U31.2(1DIR)
FTDI1_DIR2: R165.1 U31.3(2DIR)
FTDI2_DIR1: R1450.1 U62.2(1DIR)
FTDI2_DIR2: R1451.1 U62.3(2DIR)
FTDI_M40_UART0_RX: U31.12(1B2) ; also on sheet 15
FTDI_M40_UART0_TX: U31.10(2B2) ; also on sheet 15
FTDI_UART0_RX: U31.13(1B1) ; also on sheet 15
FTDI_UART0_TX: U31.11(2B1) ; also on sheet 15
FTDIA_RX: U31.6(2A1) U61.17(ADBUS1)
FTDIA_TX: U31.4(1A1) U61.16(ADBUS0)
FTDIB_RX: U31.7(2A2) U61.27(BDBUS1)
FTDIB_TX: U31.5(1A2) U61.26(BDBUS0)
FTDIC_RX: U61.39(CDBUS1) U62.6(2A1)
FTDIC_TX: U61.38(CDBUS0) U62.4(1A1)
FTDID_RX: R1449.1 TP87.1(Pin1) U61.52(DDBUS1)
FTDID_TX: TP86.1(Pin1) U61.48(DDBUS0)
IMX8_ON_OFF_BUTTON: C9.1 SW1.3(B1) SW1.4(B2) ; also on sheet 14
JTAG_POR_B: C334.1 R388.1 SW3.3(B1) SW3.4(B2) U45.3(~{MR}) U60.4(Y)
JTAG_SRST_B: J11.10(B5) R58.1 U60.1(~{OE})
JTAG_TCK: J11.4(B2) R51.2 ; also on sheet 14
JTAG_TDI: J11.8(B4) R54.1 ; also on sheet 14
JTAG_TDO: J11.6(B3) ; also on sheet 14
JTAG_TMS: J11.2(B1) R49.1 ; also on sheet 14
JTAG_VTREF: J11.1(A1) R47.1
LT_ENABLE_B: U31.14(~{2OE}) U31.15(~{1OE}) U62.14(~{2OE}) U62.15(~{1OE}) U63.4(Y)
NX20P_ACK: U15.F10(QSPI1A_SCLK) ; also on sheet 22
PMIC_POR_B_1V8: U44.2(A) ; also on sheet 6 11 14
PMIC_WDOG_IN: U41.4(Y) ; also on sheet 6 11
POR_B_1V8: R120.1 U8.1(B) U9.1(B) U44.4(Y)
PTN5110_ALERT_B: U15.D12(QSPI1A_DATA0) ; also on sheet 22
QSPI0_DAT0: U15.G13(QSPI0A_DATA0) U47.D3(DQ0)
QSPI0_DAT1: U15.F14(QSPI0A_DATA1) U47.D2(DQ1)
QSPI0_DAT2: R123.1 U15.H14(QSPI0A_DATA2) U47.C4(DQ2/~{W})
QSPI0_DAT3: U15.H16(QSPI0A_DATA3) U47.D4(DQ3)
QSPI0_DAT4: U15.H18(QSPI0B_DATA0) U47.D5(DQ4)
QSPI0_DAT5: U15.H20(QSPI0B_DATA1) U47.E3(DQ5)
QSPI0_DAT6: U15.G19(QSPI0B_DATA2) U47.E2(DQ6)
QSPI0_DAT7: U15.F20(QSPI0B_DATA3) U47.E1(DQ7)
QSPI0_DQS: U15.G17(QSPI0A_DQS) U47.C3(DQS)
QSPI0A_CLK: U15.E17(QSPI0A_SCLK) U47.B2(C)
QSPI0A_CS_B: R124.1 U15.E15(QSPI0A_SS0_B) U47.C2(~{S})
QSPI0B_CLK: U15.F18(QSPI0B_SCLK) U47.B1(RFU3)
QSPI0B_CS_B: R118.1 U15.F22(QSPI0B_SS0_B) U47.A3(RFU2)
QSPI_RST_B: R119.1 R120.2 U47.A4(~{RESET})
RTCK: J11.7(A4) R52.2
SCU_BOOT_MODE0: R43.2 SW2.1 ; also on sheet 14
SCU_BOOT_MODE1: R41.2 SW2.2 ; also on sheet 14
SCU_BOOT_MODE2: R33.2 SW2.3 ; also on sheet 14
SCU_BOOT_MODE3: R21.2 SW2.4 ; also on sheet 14
SCU_BOOT_MODE4: R18.2 SW2.5 ; also on sheet 14
SCU_BOOT_MODE5: R16.2 SW2.6 ; also on sheet 14
SCU_DEBUG_LED(SCU_GPIO0_02): Q2.1(GATE) R12.2 ; also on sheet 14
SCU_PMIC_STANDBY: Q1.1(GATE) R13.2 ; also on sheet 6 11 14
SCU_UART0_RX: U62.13(1B1) ; also on sheet 14
SCU_UART0_TX: R1454.2 U62.11(2B1) ; also on sheet 14
SCU_WDOG_OUT: U41.2(A) ; also on sheet 14
SENSORS_INT_B(USDHC2_WP): U15.D8(USDHC2_WP) ; also on sheet 28
USDHC1_CD_B: D17.1(C1) J19.10(CARD_DETECT) R179.1 U15.H42(USDHC1_DATA7)
USDHC1_CLK: D20.1(C1) J19.5(CLK) U15.J39(USDHC1_CLK)
USDHC1_CMD: D21.1(C1) J19.2(CMD) U15.G41(USDHC1_CMD)
USDHC1_DAT0: D19.1(C1) J19.7(DAT0) U15.E37(USDHC1_DATA0)
USDHC1_DAT1: D18.1(C1) J19.8(DAT1) U15.F38(USDHC1_DATA1)
USDHC1_DAT2: D23.1(C1) J19.9(DAT2) U15.E39(USDHC1_DATA2)
USDHC1_DAT3: D22.1(C1) J19.1(CD/DAT3) U15.F40(USDHC1_DATA3)
USDHC1_RESET_B: R174.1 U15.A5(USDHC1_RESET_B) U32.A3(EN)
USDHC1_VSELECT: U15.B4(USDHC1_VSELECT) ; also on sheet 11
USDHC1_WP: D24.1(C1) J19.11(WRITE_PROTECT) R178.1 U15.F42(USDHC1_DATA6)
USDHC2_VSELECT: U15.A7(USDHC2_VSELECT) ; also on sheet 6
WIFI_BT_SDIO_CLK: R106.2 ; also on sheet 26
WIFI_BT_SDIO_CMD: R105.2 ; also on sheet 26
WIFI_BT_SDIO_DAT0: R91.2 ; also on sheet 26
WIFI_BT_SDIO_DAT1: R114.2 ; also on sheet 26
WIFI_BT_SDIO_DAT2: R101.2 ; also on sheet 26
WIFI_BT_SDIO_DAT3: R99.2 ; also on sheet 26
WIFI_EN(WIFI_RST_B): U15.C7(USDHC2_RESET_B) ; also on sheet 26
N2200937: Q2.3(DRAIN) R223.1
N2201244: Q1.3(DRAIN) R14.1
N2201839: D4.C(CATHODE) R14.2
N15049515: R106.1 R283.1 U15.F46(USDHC2_CLK)
N15049535: R105.1 R282.1 U15.H44(USDHC2_CMD)
N15055242: R91.1 R270.1 U15.H48(USDHC2_DATA0)
N15055246: R114.1 R284.1 U15.G45(USDHC2_DATA1)
N15055250: R101.1 R277.1 U15.L45(USDHC2_DATA2)
N15055254: R99.1 R274.1 U15.J45(USDHC2_DATA3)
N16358923: J11.9(A5) TP20.1(Pin1)
N16501422: R157.2 R158.1 U53.U5(~{RST})
N18432630: R389.2 R390.1 U44.1(B)
N18981558: C550.2 J18.6(SHELL1) J18.7(SHELL2) J18.8(SHELL3) J18.9(SHELL4) J18.10(SHELL5) R371.2
N18981592: C551.1 FB8.1 J18.1(VBUS)
N18999756: C539.1 U57.4(BP)
N19007369: U41.1(B) U42.4(Y)
N19010399: D3.C(CATHODE) R223.2
N19016433: R42.1 SW2.12
N19016436: R40.1 SW2.11
N19016439: R32.1 SW2.10
N19016442: R20.1 SW2.9
N19016445: R17.1 SW2.8
N19016448: R15.1 SW2.7
N19020913: R176.2 U32.B3(SEL)
N21375189: C1717.1 C1718.1 L30.2 U61.4(VPHY)
N21375270: C1719.1 C1720.1 L31.2 U61.9(VPLL)
N21375716: R1428.1 U61.6(REF)
N21558756: R1480.2 U62.10(2B2)
N21559964: R1479.1 U62.5(1A2)

Not connected (* = marked no-connect by the designer): J18 4(ID)*; U8 5(NC)*; U9 5(NC)*; U15 F16(QSPI0A_SS1_B)* H22(QSPI0B_DQS)* H24(QSPI0B_SS1_B)*; U42 1(NC)*; U44 5(NC)*; U47 A2(RFU1)* A5(DNU1)* B5(DNU2)*; U53 A4(NC)* A6(NC)* A9(NC)* A11(NC)* AA1(NC)* AA2(NC)* AA7(NC)* AA8(NC)* AA9(NC)* AA10(RFU)* AA11(NC)* AA12(NC)* AA13(NC)* AA14(NC)* AE1(NC)* AE14(NC)* AG2(NC)* AG13(NC)* AH4(NC)* AH6(NC)* AH9(NC)* AH11(NC)* B2(NC)* B13(NC)* D1(NC)* D14(NC)* H1(NC)* H2(NC)* H7(RFU)* H8(NC)* H9(NC)* H10(NC)* H11(NC)* H12(NC)* H13(NC)* H14(NC)* J1(NC)* J7(NC)* J8(NC)* J9(NC)* J10(NC)* J11(NC)* J12(NC)* J13(NC)* J14(NC)* K1(NC)* K3(NC)* K5(RFU)* K7(NC)* K8(NC)* K9(NC)* K10(NC)* K11(NC)* K12(NC)* K13(NC)* K14(NC)* L1(NC)* L2(NC)* L3(NC)* L4(NC)* L12(NC)* L13(NC)* L14(NC)* M1(NC)* M2(NC)* M3(NC)* M5(RFU)* M8(RFU)* M9(RFU)* M10(RFU)* M12(NC)* M13(NC)* M14(NC)* N1(NC)* N2(NC)* N3(NC)* N10(RFU)* N12(NC)* N13(NC)* N14(NC)* P1(NC)* P2(NC)* P3(RFU)* P10(RFU)* P12(NC)* P13(NC)* P14(NC)* R1(NC)* R2(NC)* R3(NC)* R12(NC)* R13(NC)* R14(NC)* T1(NC)* T2(NC)* T3(NC)* T12(NC)* T13(NC)* T14(NC)* U1(NC)* U2(NC)* U3(NC)* U6(RFU)* U7(RFU)* U10(RFU)* U12(NC)* U13(NC)* U14(NC)* V1(NC)* V2(NC)* V3(NC)* V12(NC)* V13(NC)* V14(NC)* W1(NC)* W2(NC)* W3(NC)* W7(NC)* W8(NC)* W9(NC)* W10(NC)* W11(NC)* W12(NC)* W13(NC)* W14(NC)* Y1(NC)* Y3(NC)* Y6(NC)* Y7(NC)* Y8(NC)* Y9(NC)* Y10(NC)* Y11(NC)* Y12(NC)* Y13(NC)* Y14(NC)*; U61 18(ADBUS2)* 19(ADBUS3)* 21(ADBUS4)* 22(ADBUS5)* 23(ADBUS6)* 24(ADBUS7)* 28(BDBUS2)* 29(BDBUS3)* 30(BDBUS4)* 32(BDBUS5)* 33(BDBUS6)* 34(BDBUS7)* 40(CDBUS2)* 41(CDBUS3)* 43(CDBUS4)* 44(CDBUS5)* 45(CDBUS6)* 46(CDBUS7)* 53(DDBUS2)* 54(DDBUS3)* 55(DDBUS4)* 57(DDBUS5)* 58(DDBUS6)* 59(DDBUS7)* 60(~{PWREN})* 62(EECLK)*; U62 7(2A2)* 12(1B2)*; U63 1(NC)*

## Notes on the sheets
sheet 18
- eMMC
- I/O VOLTAGE :1.8V
- MLB not supported by the processor.
- I/O VOLTAGE :1.8V
- 10K IS PROVIDED AS PER
  THE RECOMMENDATION IN
  DATASHEET
- B2B CONNECTOR
- WIFI BT SDIO INTERFACE IS 1.8V,SOFTWARE MUST
  CONFIGURE USDHC2_VSELECT ACCORDING TO THIS
- SD CARD INTERFACE
- SDXC Power Control
- Bulk capacitance already present in this rail
  (C225)
- SEL Input has Internal Pulldown(700k)
sheet 19
- BOOT CONFIGURATIONS
- BOOT MODE
  MODE           5   4   3   2   1   0
  ====================================
  FUSE           0   0   0   0   0   0
  SERIAL BOOT    0   0   0   1   0   0
  eMMC0          0   0   1   0   0   0
  SD1            0   0   1   1   0   0
  Octal SPI      0   1   1   0   0   0
- OCTAL/XSPI/QSPI FLASH
- Use Pad sharing for these 2 RES
- I/O VOLTAGE :1.8V
- I/O VOLTAGE :3.3V
- B2B CONNECTOR
sheet 20
- SYSTEM ON/OFF
- RESET GENERATION
- * Hold SW1 for 5 sec for force OFF
  * Hold SW1 for 0.5 sec to turn ON
- RESET SWITCH
- 2.63V Threshold
- 210 ms delay
- Open-Drain RST output
- Internal 100k Pullup on MR input
- Idd = 10 uA max
- LED INDICATIONS
- SCU Debug GPIO-2
  Hi = on
  Lo = off
- SCU_PMIC_STANDBY
  Hi = on = STBY
  Lo = off = Run
- JTAG
- MX8QM On-Chip 50 kohm Pulls
  ---------------------------
  JTAG_TMS = PU
  JTAG_TCK = PD
  JTAG_TDI = PU
  JTAG_TRST_B = PU
  TEST_MODE_SELECT = PD
sheet 21
- DEBUG UART-USB
- MICRO USB DEBUG CONNECTOR
- 90-Ohm
  differential
  pair
- Layout Note: Place resistors
  R192 and R191 close to
  USB connector J18.
